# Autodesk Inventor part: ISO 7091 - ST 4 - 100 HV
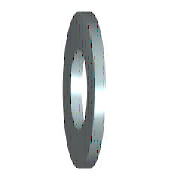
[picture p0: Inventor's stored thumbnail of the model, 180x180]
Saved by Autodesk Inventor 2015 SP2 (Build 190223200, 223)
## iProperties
IsCustomPart: 0
Created: 2012-02
Part Number: ISO 7091 - ST 4 - 100 HV
Material: Stahl
Description: Unterlegscheiben - normale Ausführung - Produktklasse C
Document SubType Name: Modeling
Standard: ISO 7091
Designer: Hübner
Standard Revision: Second edition 2000-06-01
Standards Organization: ISO
Language: de-DE
Size Designation: ST 4 - 100 HV
Categories: <MemberInstance><Categories><Category DisplayName="Verbindungselemente" InternalName="e4da775c-781d-43d5-af7c-5136215cf5a6" Mnemonic="FSTN"><Category DisplayNam
Density: 7.85 g/cm^3
Appearance: Platte
Author: Hübner
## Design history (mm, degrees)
sketch "Skizze"
  geometry: C1 r 5 at (0, 0); C2 r 2.25 at (0, 0); 1 further point
  constraints: 2 centre point, 2 coincident
  dimensions: "d0" = 4.5 diameter of C2 (= SD1); "d1" = 10 diameter of C1 (= SD2)
extrude "Körper" new body sketch "Skizze" distance "d2" = 1 (= SD); taper "d3" = 0 deg
workaxis "Work Axis1"
workplane "Work Plane1"
body "Solid1"
other parameters: "SD1" = 4.5 [user parameter; used in 1 equation term], "SD2" = 10 [user parameter; used in 1 equation term], "SD" = 1 [user parameter; used in 1 equation term], "d4" = 0, "d5" = 0, "d6" = 0, "d7" = 0, "NND" = 4 [user parameter]
